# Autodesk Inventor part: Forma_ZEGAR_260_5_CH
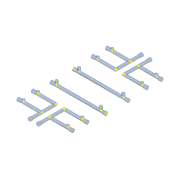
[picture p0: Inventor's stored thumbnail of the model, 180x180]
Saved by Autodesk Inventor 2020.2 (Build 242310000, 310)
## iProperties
Created: 2015-01
Part Number: Forma_ZEGAR_260_5_CH
Material: Ogólny
Document SubType Name: Modeling
Designer: F.Stasiak
Density: 1 g/cm^3
Appearance: Przezroczysty - niebieski
Catalog Web Link: www.expertbooks.pl
Manager: www.cadconsulting.pl
Company: Fabian Stasiak CAD Consulting
Author: F.Stasiak
Subject: Zbiór ćwiczeń. Autodesk Inventor 2020. Kurs Professional
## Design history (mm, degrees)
node "Płaszczyzna konstrukcyjna1"
node "Segment chłodzenia1"
  sketch "Szkic1"
    geometry: L1 (0, 0)-(0, -5.177); L2 (0, -5.177)-(6.924, -4.745); L3 (6.924, -4.745)-(6.924, -4); L4 (6.924, -4)-(149.076, -4); L5 (149.076, -4)-(149.076, -4.745); L6 (149.076, -4.745)-(156, -5.177); L7 (156, -5.177)-(156, 0); L8 (0, 0)-(156, 0)
    constraints: 16 end point, 4 perpendicular, 1 parallel
    dimensions: "d0" = 4 distance between parallel lines of L4 L8; "d1" = 6.92404 distance between parallel lines of L3 L1; "d2" = 6.92404 distance between parallel lines of L5 L7; "d3" = 93.5763 deg angle of L2 L3; "d4" = 0.74472 distance of L2.end L3.end; "d5" = 93.5763 deg angle of L6 L5; "d6" = 0.74472 distance of L4.end L5.end
  node "Punkt konstrukcyjny1"
  node "Oś konstrukcyjna1"
node "Płaszczyzna konstrukcyjna3"
node "Segment chłodzenia3"
  sketch "Szkic3"
    geometry: L1 (0, 0)-(0, -5.177); L2 (0, -5.177)-(6.924, -4.745); L3 (6.924, -4.745)-(6.924, -4); L4 (6.924, -4)-(68, -4); L5 (68, -4)-(70.403, 0); L6 (70.403, 0)-(68, 0); L7 (0, 0)-(68, 0)
    constraints: 14 end point, 2 perpendicular, 1 collinear, 1 parallel
    dimensions: "d18" = 4 distance between parallel lines of L4 L7; "d19" = 2.40344 distance of L5.end L6.end; "d20" = 6.92404 distance between parallel lines of L3 L1; "d21" = 93.5763 deg angle of L2 L3; "d22" = 0.74472 distance of L2.end L3.end; "d23" = 59 deg angle of L5 L7
  node "Punkt konstrukcyjny3"
  node "Oś konstrukcyjna3"
node "Płaszczyzna konstrukcyjna4"
node "Segment chłodzenia4"
  sketch "Szkic4"
    geometry: L1 (0, 0)-(0, -5.177); L2 (0, -5.177)-(6.924, -4.745); L3 (6.924, -4.745)-(6.924, -4); L4 (6.924, -4)-(68, -4); L5 (68, -4)-(70.403, 0); L6 (70.403, 0)-(68, 0); L7 (0, 0)-(68, 0)
    constraints: 14 end point, 2 perpendicular, 1 collinear, 1 parallel
    dimensions: "d26" = 4 distance between parallel lines of L4 L7; "d27" = 2.40344 distance of L5.end L6.end; "d28" = 6.92404 distance between parallel lines of L3 L1; "d29" = 93.5763 deg angle of L2 L3; "d30" = 0.74472 distance of L2.end L3.end; "d31" = 59 deg angle of L5 L7
  node "Punkt konstrukcyjny4"
  node "Oś konstrukcyjna4"
node "Płaszczyzna konstrukcyjna5"
node "Segment chłodzenia5"
  sketch "Szkic5"
    geometry: L1 (0, 0)-(0, -5.177); L2 (0, -5.177)-(6.924, -4.745); L3 (6.924, -4.745)-(6.924, -4); L4 (6.924, -4)-(75, -4); L5 (75, -4)-(77.403, 0); L6 (77.403, 0)-(75, 0); L7 (0, 0)-(75, 0)
    constraints: 14 end point, 2 perpendicular, 1 collinear, 1 parallel
    dimensions: "d34" = 4 distance between parallel lines of L4 L7; "d35" = 2.40344 distance of L5.end L6.end; "d36" = 6.92404 distance between parallel lines of L3 L1; "d37" = 93.5763 deg angle of L2 L3; "d38" = 0.74472 distance of L2.end L3.end; "d39" = 59 deg angle of L5 L7
  node "Punkt konstrukcyjny5"
  node "Oś konstrukcyjna5"
node "Płaszczyzna konstrukcyjna6"
node "Segment chłodzenia6"
  sketch "Szkic6"
    geometry: L1 (0, 0)-(0, -4); L2 (0, -4)-(7, -4); L3 (7, -4)-(9.403, 0); L4 (9.403, 0)-(7, 0); L5 (0, 0)-(7, 0)
    constraints: 10 end point, 1 collinear, 1 parallel, 1 perpendicular
    dimensions: "d42" = 4 distance between parallel lines of L2 L5; "d43" = 2.40344 distance of L3.end L4.end; "d44" = 59 deg angle of L3 L5
  node "Punkt konstrukcyjny6"
  node "Oś konstrukcyjna6"
node "Płaszczyzna konstrukcyjna7"
node "Segment chłodzenia7"
  sketch "Szkic7"
    geometry: L1 (0, 0)-(0, -4); L2 (0, -4)-(7, -4); L3 (7, -4)-(9.403, 0); L4 (9.403, 0)-(7, 0); L5 (0, 0)-(7, 0)
    constraints: 10 end point, 1 collinear, 1 parallel, 1 perpendicular
    dimensions: "d47" = 4 distance between parallel lines of L2 L5; "d48" = 2.40344 distance of L3.end L4.end; "d49" = 59 deg angle of L3 L5
  node "Punkt konstrukcyjny7"
  node "Oś konstrukcyjna7"
node "Płaszczyzna konstrukcyjna9"
node "Segment chłodzenia9"
  sketch "Szkic9"
    geometry: L1 (0, 0)-(0, -4); L2 (0, -4)-(12, -4); L3 (12, -4)-(14.403, 0); L4 (14.403, 0)-(12, 0); L5 (0, 0)-(12, 0)
    constraints: 10 end point, 1 collinear, 1 parallel, 1 perpendicular
    dimensions: "d57" = 4 distance between parallel lines of L2 L5; "d58" = 2.40344 distance of L3.end L4.end; "d59" = 59 deg angle of L3 L5
  node "Punkt konstrukcyjny9"
  node "Oś konstrukcyjna9"
node "Płaszczyzna konstrukcyjna10"
node "Segment chłodzenia10"
  sketch "Szkic10"
    geometry: L1 (0, 0)-(0, -4); L2 (0, -4)-(12, -4); L3 (12, -4)-(14.403, 0); L4 (14.403, 0)-(12, 0); L5 (0, 0)-(12, 0)
    constraints: 10 end point, 1 collinear, 1 parallel, 1 perpendicular
    dimensions: "d62" = 4 distance between parallel lines of L2 L5; "d63" = 2.40344 distance of L3.end L4.end; "d64" = 59 deg angle of L3 L5
  node "Punkt konstrukcyjny10"
  node "Oś konstrukcyjna10"
node "Płaszczyzna konstrukcyjna12"
node "Segment chłodzenia12"
  sketch "Szkic12"
    geometry: L1 (0, 0)-(0, -5.177); L2 (0, -5.177)-(6.924, -4.745); L3 (6.924, -4.745)-(6.924, -4); L4 (6.924, -4)-(68, -4); L5 (68, -4)-(70.403, 0); L6 (70.403, 0)-(68, 0); L7 (0, 0)-(68, 0)
    constraints: 14 end point, 2 perpendicular, 1 collinear, 1 parallel
    dimensions: "d72" = 4 distance between parallel lines of L4 L7; "d73" = 2.40344 distance of L5.end L6.end; "d74" = 6.92404 distance between parallel lines of L3 L1; "d75" = 93.5763 deg angle of L2 L3; "d76" = 0.74472 distance of L2.end L3.end; "d77" = 59 deg angle of L5 L7
  node "Punkt konstrukcyjny12"
  node "Oś konstrukcyjna12"
node "Płaszczyzna konstrukcyjna13"
node "Segment chłodzenia13"
  sketch "Szkic13"
    geometry: L1 (0, 0)-(0, -5.178); L2 (0, -5.178)-(6.924, -4.744); L3 (6.924, -4.744)-(6.924, -4); L4 (6.924, -4)-(68, -4); L5 (68, -4)-(70.403, 0); L6 (70.403, 0)-(68, 0); L7 (0, 0)-(68, 0)
    constraints: 14 end point, 2 perpendicular, 1 collinear, 1 parallel
    dimensions: "d80" = 4 distance between parallel lines of L4 L7; "d81" = 2.40344 distance of L5.end L6.end; "d82" = 6.924 distance between parallel lines of L3 L1; "d83" = 93.58 deg angle of L2 L3; "d84" = 0.7445 distance of L2.end L3.end; "d85" = 59 deg angle of L5 L7
  node "Punkt konstrukcyjny13"
  node "Oś konstrukcyjna13"
node "Płaszczyzna konstrukcyjna14"
node "Segment chłodzenia14"
  sketch "Szkic14"
    geometry: L1 (0, 0)-(0, -5.178); L2 (0, -5.178)-(6.924, -4.745); L3 (6.924, -4.745)-(6.924, -4); L4 (6.924, -4)-(75, -4); L5 (75, -4)-(77.403, 0); L6 (77.403, 0)-(75, 0); L7 (0, 0)-(75, 0)
    constraints: 14 end point, 2 perpendicular, 1 collinear, 1 parallel
    dimensions: "d88" = 4 distance between parallel lines of L4 L7; "d89" = 2.40344 distance of L5.end L6.end; "d90" = 6.924 distance between parallel lines of L3 L1; "d91" = 93.58 deg angle of L2 L3; "d92" = 0.7445 distance of L2.end L3.end; "d93" = 59 deg angle of L5 L7
  node "Punkt konstrukcyjny14"
  node "Oś konstrukcyjna14"
node "Płaszczyzna konstrukcyjna15"
node "Segment chłodzenia15"
  sketch "Szkic15"
    geometry: L1 (0, 0)-(0, -4); L2 (0, -4)-(7, -4); L3 (7, -4)-(9.403, 0); L4 (9.403, 0)-(7, 0); L5 (0, 0)-(7, 0)
    constraints: 10 end point, 1 collinear, 1 parallel, 1 perpendicular
    dimensions: "d96" = 4 distance between parallel lines of L2 L5; "d97" = 2.40344 distance of L3.end L4.end; "d98" = 59 deg angle of L3 L5
  node "Punkt konstrukcyjny15"
  node "Oś konstrukcyjna15"
node "Płaszczyzna konstrukcyjna16"
node "Segment chłodzenia16"
  sketch "Szkic16"
    geometry: L1 (0, 0)-(0, -4); L2 (0, -4)-(7, -4); L3 (7, -4)-(9.403, 0); L4 (9.403, 0)-(7, 0); L5 (0, 0)-(7, 0)
    constraints: 10 end point, 1 collinear, 1 parallel, 1 perpendicular
    dimensions: "d101" = 4 distance between parallel lines of L2 L5; "d102" = 2.40344 distance of L3.end L4.end; "d103" = 59 deg angle of L3 L5
  node "Punkt konstrukcyjny16"
  node "Oś konstrukcyjna16"
node "Płaszczyzna konstrukcyjna17"
node "Segment chłodzenia17"
  sketch "Szkic17"
    geometry: L1 (0, 0)-(0, -5.178); L2 (0, -5.178)-(6.924, -4.745); L3 (6.924, -4.745)-(6.924, -4); L4 (6.924, -4)-(149.076, -4); L5 (149.076, -4)-(149.076, -4.745); L6 (149.076, -4.745)-(156, -5.178); L7 (156, -5.178)-(156, 0); L8 (0, 0)-(156, 0)
    constraints: 16 end point, 4 perpendicular, 1 parallel
    dimensions: "d106" = 4 distance between parallel lines of L4 L8; "d107" = 6.924 distance between parallel lines of L3 L1; "d108" = 6.924 distance between parallel lines of L5 L7; "d109" = 93.58 deg angle of L2 L3; "d110" = 0.7445 distance of L2.end L3.end; "d111" = 93.58 deg angle of L6 L5; "d112" = 0.7445 distance of L4.end L5.end
  node "Punkt konstrukcyjny17"
  node "Oś konstrukcyjna17"
node "Płaszczyzna konstrukcyjna19"
node "Segment chłodzenia19"
  sketch "Szkic19"
    geometry: L1 (0, 0)-(0, -5.178); L2 (0, -5.178)-(6.924, -4.745); L3 (6.924, -4.745)-(6.924, -4); L4 (6.924, -4)-(68, -4); L5 (68, -4)-(68, 0); L6 (0, 0)-(68, 0)
    constraints: 12 end point, 3 perpendicular, 1 parallel
    dimensions: "d124" = 4 distance between parallel lines of L4 L6; "d125" = 6.924 distance between parallel lines of L3 L1; "d126" = 93.58 deg angle of L2 L3; "d127" = 0.7445 distance of L2.end L3.end
  node "Punkt konstrukcyjny19"
  node "Oś konstrukcyjna19"
node "Płaszczyzna konstrukcyjna20"
node "Segment chłodzenia20"
  sketch "Szkic20"
    geometry: L1 (0, 0)-(0, -5.178); L2 (0, -5.178)-(6.924, -4.745); L3 (6.924, -4.745)-(6.924, -4); L4 (6.924, -4)-(68, -4); L5 (68, -4)-(68, 0); L6 (0, 0)-(68, 0)
    constraints: 12 end point, 3 perpendicular, 1 parallel
    dimensions: "d130" = 4 distance between parallel lines of L4 L6; "d131" = 6.924 distance between parallel lines of L3 L1; "d132" = 93.58 deg angle of L2 L3; "d133" = 0.7445 distance of L2.end L3.end
  node "Punkt konstrukcyjny20"
  node "Oś konstrukcyjna20"
node "Płaszczyzna konstrukcyjna21"
node "Segment chłodzenia21"
  sketch "Szkic21"
    geometry: L1 (0, 0)-(0, -5.178); L2 (0, -5.178)-(6.924, -4.745); L3 (6.924, -4.745)-(6.924, -4); L4 (6.924, -4)-(75, -4); L5 (75, -4)-(75, 0); L6 (0, 0)-(75, 0)
    constraints: 12 end point, 3 perpendicular, 1 parallel
    dimensions: "d136" = 4 distance between parallel lines of L4 L6; "d137" = 6.924 distance between parallel lines of L3 L1; "d138" = 93.58 deg angle of L2 L3; "d139" = 0.7445 distance of L2.end L3.end
  node "Punkt konstrukcyjny21"
  node "Oś konstrukcyjna21"
node "Płaszczyzna konstrukcyjna22"
node "Segment chłodzenia22"
  sketch "Szkic22"
    geometry: L1 (0, 0)-(0, -5.178); L2 (0, -5.178)-(6.924, -4.744); L3 (6.924, -4.744)-(6.924, -4); L4 (6.924, -4)-(68, -4); L5 (68, -4)-(68, 0); L6 (0, 0)-(68, 0)
    constraints: 12 end point, 3 perpendicular, 1 parallel
    dimensions: "d142" = 4 distance between parallel lines of L4 L6; "d143" = 6.924 distance between parallel lines of L3 L1; "d144" = 93.58 deg angle of L2 L3; "d145" = 0.7445 distance of L2.end L3.end
  node "Punkt konstrukcyjny22"
  node "Oś konstrukcyjna22"
node "Płaszczyzna konstrukcyjna23"
node "Segment chłodzenia23"
  sketch "Szkic23"
    geometry: L1 (0, 0)-(0, -5.178); L2 (0, -5.178)-(6.924, -4.744); L3 (6.924, -4.744)-(6.924, -4); L4 (6.924, -4)-(68, -4); L5 (68, -4)-(68, 0); L6 (0, 0)-(68, 0)
    constraints: 12 end point, 3 perpendicular, 1 parallel
    dimensions: "d148" = 4 distance between parallel lines of L4 L6; "d149" = 6.924 distance between parallel lines of L3 L1; "d150" = 93.58 deg angle of L2 L3; "d151" = 0.7445 distance of L2.end L3.end
  node "Punkt konstrukcyjny23"
  node "Oś konstrukcyjna23"
node "Płaszczyzna konstrukcyjna24"
node "Segment chłodzenia24"
  sketch "Szkic24"
    geometry: L1 (0, 0)-(0, -5.178); L2 (0, -5.178)-(6.924, -4.745); L3 (6.924, -4.745)-(6.924, -4); L4 (6.924, -4)-(75, -4); L5 (75, -4)-(75, 0); L6 (0, 0)-(75, 0)
    constraints: 12 end point, 3 perpendicular, 1 parallel
    dimensions: "d154" = 4 distance between parallel lines of L4 L6; "d155" = 6.924 distance between parallel lines of L3 L1; "d156" = 93.58 deg angle of L2 L3; "d157" = 0.7445 distance of L2.end L3.end
  node "Punkt konstrukcyjny24"
  node "Oś konstrukcyjna24"
node "Płaszczyzna konstrukcyjna25"
node "Segment chłodzenia25"
  sketch "Szkic25"
    geometry: L1 (0, 0)-(0, -4); L2 (0, -4)-(12, -4); L3 (12, -4)-(12, 0); L4 (0, 0)-(12, 0)
    constraints: 8 end point, 2 perpendicular, 1 parallel
    dimensions: "d160" = 4 distance between parallel lines of L2 L4
  node "Punkt konstrukcyjny25"
  node "Oś konstrukcyjna25"
node "Płaszczyzna konstrukcyjna27"
node "Segment chłodzenia27"
  sketch "Szkic27"
    geometry: L1 (0, 0)-(0, -4); L2 (0, -4)-(12, -4); L3 (12, -4)-(12, 0); L4 (0, 0)-(12, 0)
    constraints: 8 end point, 2 perpendicular, 1 parallel
    dimensions: "d166" = 4 distance between parallel lines of L2 L4
  node "Punkt konstrukcyjny27"
  node "Oś konstrukcyjna27"
node "Płaszczyzna konstrukcyjna29"
node "Segment chłodzenia29"
  sketch "Szkic29"
    geometry: L1 (0, 0)-(0, -4); L2 (0, -4)-(7, -4); L3 (7, -4)-(7, 0); L4 (0, 0)-(7, 0)
    constraints: 8 end point, 2 perpendicular, 1 parallel
    dimensions: "d172" = 4 distance between parallel lines of L2 L4
  node "Punkt konstrukcyjny29"
  node "Oś konstrukcyjna29"
node "Płaszczyzna konstrukcyjna30"
node "Segment chłodzenia30"
  sketch "Szkic30"
    geometry: L1 (0, 0)-(0, -4); L2 (0, -4)-(7, -4); L3 (7, -4)-(7, 0); L4 (0, 0)-(7, 0)
    constraints: 8 end point, 2 perpendicular, 1 parallel
    dimensions: "d175" = 4 distance between parallel lines of L2 L4
  node "Punkt konstrukcyjny30"
  node "Oś konstrukcyjna30"
node "Płaszczyzna konstrukcyjna31"
node "Segment chłodzenia31"
  sketch "Szkic31"
    geometry: L1 (0, 0)-(0, -4); L2 (0, -4)-(7, -4); L3 (7, -4)-(7, 0); L4 (0, 0)-(7, 0)
    constraints: 8 end point, 2 perpendicular, 1 parallel
    dimensions: "d178" = 4 distance between parallel lines of L2 L4
  node "Punkt konstrukcyjny31"
  node "Oś konstrukcyjna31"
node "Płaszczyzna konstrukcyjna32"
node "Segment chłodzenia32"
  sketch "Szkic32"
    geometry: L1 (0, 0)-(0, -4); L2 (0, -4)-(7, -4); L3 (7, -4)-(7, 0); L4 (0, 0)-(7, 0)
    constraints: 8 end point, 2 perpendicular, 1 parallel
    dimensions: "d181" = 4 distance between parallel lines of L2 L4
  node "Punkt konstrukcyjny32"
  node "Oś konstrukcyjna32"
node "Bryła1"
revolve "Obrót1" stored, may be unused: angle "d7" = 0 deg
body "Srf1"
revolve "Obrót3" stored, may be unused: angle "d24" = 0 deg
body "Srf3"
revolve "Obrót4" stored, may be unused: angle "d32" = 0 deg
body "Srf4"
revolve "Obrót5" stored, may be unused: angle "d40" = 0 deg
body "Srf5"
revolve "Obrót6" stored, may be unused: angle "d45" = 0 deg
body "Srf6"
revolve "Obrót7" stored, may be unused: angle "d50" = 0 deg
body "Srf7"
revolve "Obrót9" stored, may be unused: angle "d60" = 0 deg
body "Srf9"
revolve "Obrót10" stored, may be unused: angle "d65" = 0 deg
body "Srf10"
revolve "Obrót12" stored, may be unused: angle "d78" = 0 deg
body "Srf12"
revolve "Obrót13" stored, may be unused: angle "d86" = 0 deg
body "Srf13"
revolve "Obrót14" stored, may be unused: angle "d94" = 0 deg
body "Srf14"
revolve "Obrót15" stored, may be unused: angle "d99" = 0 deg
body "Srf15"
revolve "Obrót16" stored, may be unused: angle "d104" = 0 deg
body "Srf16"
revolve "Obrót17" stored, may be unused: angle "d113" = 0 deg
body "Srf17"
revolve "Obrót19" stored, may be unused: angle "d128" = 0 deg
body "Srf19"
revolve "Obrót20" stored, may be unused: angle "d134" = 0 deg
body "Srf20"
revolve "Obrót21" stored, may be unused: angle "d140" = 0 deg
body "Srf21"
revolve "Obrót22" stored, may be unused: angle "d146" = 0 deg
body "Srf22"
revolve "Obrót23" stored, may be unused: angle "d152" = 0 deg
body "Srf23"
revolve "Obrót24" stored, may be unused: angle "d158" = 0 deg
body "Srf24"
revolve "Obrót25" stored, may be unused: angle "d161" = 0 deg
body "Srf25"
revolve "Obrót27" stored, may be unused: angle "d167" = 0 deg
body "Srf27"
revolve "Obrót29" stored, may be unused: angle "d173" = 0 deg
body "Srf29"
revolve "Obrót30" stored, may be unused: angle "d176" = 0 deg
body "Srf30"
revolve "Obrót31" stored, may be unused: angle "d179" = 0 deg
body "Srf31"
revolve "Obrót32" stored, may be unused: angle "d182" = 0 deg
body "Srf32"
feature "PowObrotowa1" dims angle "d8" = 0 deg
feature "PowObrotowa3" dims angle "d25" = 0 deg
feature "PowObrotowa4" dims angle "d33" = 0 deg
feature "PowObrotowa5" dims angle "d41" = 0 deg
feature "PowObrotowa6" dims angle "d46" = 0 deg
feature "PowObrotowa7" dims angle "d51" = 0 deg
feature "PowObrotowa9" dims angle "d61" = 0 deg
feature "PowObrotowa10" dims angle "d66" = 0 deg
feature "PowObrotowa12" dims angle "d79" = 0 deg
feature "PowObrotowa13" dims angle "d87" = 0 deg
feature "PowObrotowa14" dims angle "d95" = 0 deg
feature "PowObrotowa15" dims angle "d100" = 0 deg
feature "PowObrotowa16" dims angle "d105" = 0 deg
feature "PowObrotowa17" dims angle "d114" = 0 deg
feature "PowObrotowa19" dims angle "d129" = 0 deg
feature "PowObrotowa20" dims angle "d135" = 0 deg
feature "PowObrotowa21" dims angle "d141" = 0 deg
feature "PowObrotowa22" dims angle "d147" = 0 deg
feature "PowObrotowa23" dims angle "d153" = 0 deg
feature "PowObrotowa24" dims angle "d159" = 0 deg
feature "PowObrotowa25" dims angle "d162" = 0 deg
feature "PowObrotowa27" dims angle "d168" = 0 deg
feature "PowObrotowa29" dims angle "d174" = 0 deg
feature "PowObrotowa30" dims angle "d177" = 0 deg
feature "PowObrotowa31" dims angle "d180" = 0 deg
feature "PowObrotowa32" dims angle "d183" = 0 deg
